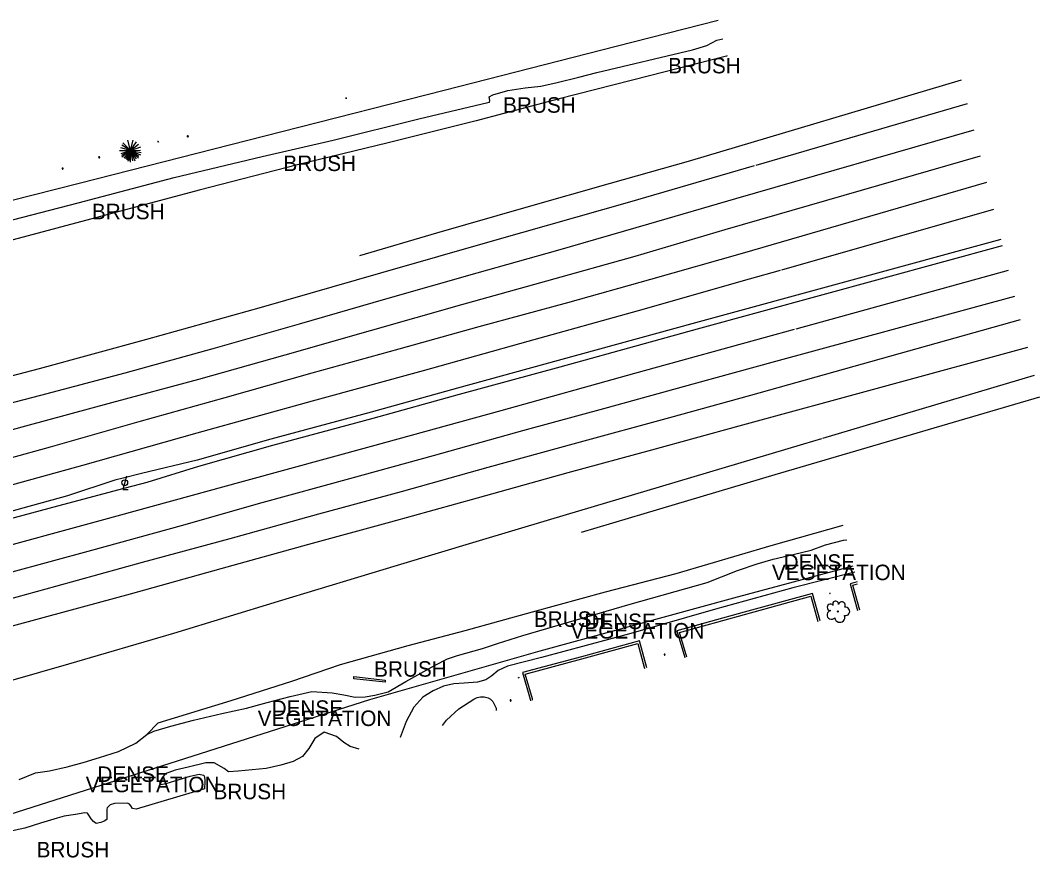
# Model space of a CAD drawing. Extents: x 2129547 to 2134906, y 657330 to 659734.
# Drawn here: x 2134392.5 to 2134852.3, y 658897.8 to 659275.8 of the extents above; entities that cross this region are included whole.
import ezdxf

# ---------------------------------------------------------------- set-up
doc = ezdxf.new("R2010")
doc.units = 0
for name, color, linetype in [('DR_X_Culvert', 7, 'Continuous'), ('LT_X_Poles', 7, 'Continuous'), ('PM_X_Edge_Line', 7, 'Continuous'), ('PM_X_Lane_Line', 7, 'Continuous'), ('PV_X_Curb', 7, 'Continuous'), ('PV_X_EOP', 7, 'Continuous'), ('PV_X_Parking_Lot', 7, 'Continuous'), ('PV_X_Shoulder', 7, 'Continuous'), ('RD_X_Concrete_Barrier', 7, 'Continuous'), ('RD_X_Fence', 7, 'Continuous'), ('VG_X_Cells', 7, 'Continuous'), ('VG_X_Flower_Bed', 7, 'Continuous'), ('VG_X_Shrub_Line_Lt', 7, 'Continuous'), ('VG_X_Text', 7, 'Continuous'), ('VG_X_Tree_Line_Lt', 7, 'Continuous')]:
    doc.layers.add(name, color=color, linetype=linetype)

msp = doc.modelspace()

# ---------------------------------------------------------------- linework, layer by layer
at = {"layer": 'DR_X_Culvert'}
msp.add_lwpolyline([(2134557, 658977), (2134542.86, 658978.58), (2134542.97, 658979.58), (2134557.11, 658977.99)], close=True, dxfattribs=at)
at = {"layer": 'LT_X_Poles'}
for points in [[(2134440.31, 659070.03), (2134438.74, 659064.05), (2134441.1, 659064.05)], [(2134757.71, 659017.31), (2134757.64, 659017.01), (2134757.75, 659017.01)], [(2134617.32, 658979.24), (2134617.24, 658978.94), (2134617.36, 658978.94)]]:
    msp.add_lwpolyline(points, dxfattribs=at)
for centre, radius in [((2134439.53, 659067.08), 1.3), ((2134757.68, 659017.16), 0.065), ((2134617.28, 658979.09), 0.065)]:
    msp.add_circle(centre, radius, dxfattribs=at)
at = {"layer": 'PM_X_Edge_Line'}
for points in [[(2134723.56, 659210.16), (2134667.28, 659193.75), (2134606.38, 659176.46), (2134554.94, 659161.67), (2134501.09, 659146.16), (2134449.29, 659131.67), (2134400.95, 659118.53), (2134356.58, 659106.88), (2134317.3, 659096.98), (2134285.7, 659088.97), (2134246.38, 659079.32), (2134241.17, 659078.04)], [(2134735.23, 659162.91), (2134721.25, 659158.93), (2134671.25, 659144.73), (2134621.41, 659130.82), (2134574.26, 659117.65), (2134524.14, 659103.87), (2134472.09, 659089.42), (2134420.46, 659074.83), (2134368.59, 659060.49), (2134308.4, 659043.65), (2134263.44, 659031.51), (2134253.36, 659028.71)], [(2134259.57, 659003.55), (2134296.43, 659013.77), (2134319.19, 659019.98), (2134374.37, 659035.23), (2134428.42, 659049.97), (2134493.16, 659067.81), (2134550.8, 659083.53), (2134609.4, 659099.69), (2134669.62, 659116.56), (2134732.99, 659133.95), (2134741.79, 659136.38)], [(2134274.16, 658944.52), (2134293.12, 658950.08), (2134329.98, 658961.06), (2134360.83, 658969.97), (2134414.34, 658985.33), (2134461.66, 658999.2), (2134508.88, 659013.57), (2134562.68, 659029.83), (2134598.06, 659040.48), (2134631.84, 659050.6), (2134687.93, 659067.36), (2134745.97, 659084.59), (2134753.99, 659086.98)]]:
    msp.add_lwpolyline(points, dxfattribs=at)
at = {"layer": 'PM_X_Lane_Line'}
for points in [[(2134822.61, 659226.18), (2134715.05, 659195.24), (2134675.81, 659183.86), (2134634.77, 659171.94), (2134598.34, 659161.72), (2134557.15, 659150), (2134518.25, 659138.64), (2134480.37, 659127.86), (2134439.61, 659116.6), (2134401.46, 659106.44), (2134359.78, 659095.67), (2134309.38, 659082.83), (2134275.7, 659074.42), (2134243.98, 659066.66)], [(2134825.5, 659214.49), (2134710.32, 659181.19), (2134669.66, 659169.26), (2134629.87, 659158.12), (2134591.41, 659147.43), (2134550.2, 659135.64), (2134511.72, 659124.67), (2134472.82, 659113.69), (2134433.56, 659103.17), (2134394.83, 659092.62), (2134356.4, 659082.11), (2134319.87, 659072.09), (2134283.72, 659062.12), (2134247.56, 659052.18)], [(2134828.43, 659202.6), (2134718.15, 659170.59), (2134676.73, 659158.78), (2134639.29, 659148.33), (2134599.33, 659137.45), (2134563.14, 659127.36), (2134524.01, 659116.49), (2134484.69, 659105.4), (2134445.95, 659094.5), (2134405.86, 659083.18), (2134368.79, 659072.88), (2134329.51, 659062.05), (2134290.35, 659051.26), (2134252.68, 659040.78), (2134250.52, 659040.2)], [(2134262.4, 658992.11), (2134275.67, 658995.74), (2134315.3, 659006.74), (2134348.87, 659015.75), (2134387.16, 659026.4), (2134424.62, 659036.65), (2134465.1, 659047.8), (2134501.55, 659058.17), (2134541.08, 659069), (2134578.8, 659079.33), (2134619.16, 659090.65), (2134657.36, 659101.1), (2134696.06, 659111.65), (2134733.24, 659121.93), (2134841.12, 659151.25)], [(2134265.12, 658981.08), (2134282.76, 658985.93), (2134321.9, 658996.69), (2134368.99, 659009.55), (2134408.45, 659020.37), (2134447.57, 659031.13), (2134487.07, 659041.95), (2134527.16, 659053), (2134564.44, 659063.14), (2134603.55, 659074.07), (2134643.47, 659085.14), (2134685.5, 659096.55), (2134722.02, 659106.56), (2134843.73, 659140.7)], [(2134846.83, 659128.14), (2134716.56, 659092.63), (2134677.17, 659081.8), (2134639.44, 659071.51), (2134598.52, 659060.07), (2134559.43, 659049.32), (2134522.49, 659039.2), (2134482.86, 659028.13), (2134442.03, 659016.71), (2134404.17, 659006.55), (2134363.13, 658995.42), (2134313.89, 658982.15), (2134271.17, 658970.33), (2134268, 658969.46)]]:
    msp.add_lwpolyline(points, dxfattribs=at)
at = {"layer": 'PV_X_Curb'}
for points in [[(2134769.96, 659022.37), (2134766.88, 659021.49), (2134770.22, 659009.31)], [(2134753.29, 659004.71), (2134749.79, 659017.01), (2134718.95, 659008.56), (2134688.65, 659000.16), (2134692.18, 658988.1)], [(2134675.06, 658983.45), (2134671.73, 658995.64), (2134645.59, 658988.52), (2134618.99, 658981.33), (2134622.51, 658969.34), (2134622.6, 658968.66)]]:
    msp.add_lwpolyline(points, dxfattribs=at)
at = {"layer": 'PV_X_EOP'}
for p, q in [((2134819.64, 659238.18), (2134724.23, 659210.35)), ((2134831.46, 659190.35), (2134735.86, 659163.09)), ((2134742.44, 659136.56), (2134838.21, 659163.02)), ((2134754.5, 659087.14), (2134849.94, 659115.57))]:
    msp.add_line(p, q, dxfattribs=at)
at = {"layer": 'PV_X_Parking_Lot'}
for points in [[(2134771.19, 659009.58), (2134768.11, 659020.8), (2134770.2, 659021.4)], [(2134693.14, 658988.37), (2134689.89, 658999.47), (2134719.22, 659007.59), (2134749.09, 659015.79), (2134752.33, 659004.45)], [(2134623.57, 658968.94), (2134623.49, 658969.55), (2134620.24, 658980.63), (2134645.85, 658987.55), (2134671.03, 658994.42), (2134674.1, 658983.19)]]:
    msp.add_lwpolyline(points, dxfattribs=at)
at = {"layer": 'PV_X_Shoulder'}
for points in [[(2134816.88, 659248.86), (2134693.73, 659212.03), (2134658.59, 659202.13), (2134620.53, 659191.28), (2134580.16, 659179.66), (2134545.46, 659169.48)], [(2134852.32, 659105.7), (2134732.93, 659070.57), (2134673.81, 659053.06), (2134645.44, 659044.63)]]:
    msp.add_lwpolyline(points, dxfattribs=at)
at = {"layer": 'RD_X_Concrete_Barrier'}
for points in [[(2134834.78, 659176.9), (2134697, 659139.23), (2134635.06, 659122.19), (2134589.66, 659109.73), (2134550.72, 659098.97), (2134505.43, 659086.73), (2134472.19, 659077.25), (2134447.11, 659071.29), (2134438.78, 659069.08), (2134435.09, 659068.21), (2134413.68, 659061.14), (2134357.43, 659045.64), (2134311.42, 659032.39), (2134266.53, 659020.26), (2134256.16, 659017.38)], [(2134835.5, 659173.98), (2134697.79, 659136.33), (2134635.86, 659119.29), (2134590.45, 659106.84), (2134551.51, 659096.07), (2134506.21, 659083.83), (2134472.85, 659074.37), (2134449.45, 659067.1), (2134436.3, 659063.72), (2134405.29, 659055.38), (2134358.24, 659042.75), (2134312.22, 659029.5), (2134267.32, 659017.37), (2134256.88, 659014.47)]]:
    msp.add_lwpolyline(points, dxfattribs=at)
at = {"layer": 'RD_X_Fence'}
for points in [[(2134707.34, 659275.8), (2134661.3, 659263.97), (2134583.68, 659244.07), (2134510.36, 659225.5), (2134418.95, 659202.15), (2134325.8, 659178.53), (2134239.8, 659158.08)], [(2134330.51, 658899.2), (2134411.41, 658924.97), (2134550.15, 658969.27), (2134626.91, 658991.22), (2134714.37, 659015.06), (2134768.19, 659029.53)]]:
    msp.add_lwpolyline(points, dxfattribs=at)
at = {"layer": 'VG_X_Cells'}
for p, q in [((2134539.22, 659240.71), (2134539.46, 659240.71)), ((2134539.46, 659240.71), (2134539.24, 659240.77)), ((2134539.46, 659240.71), (2134539.25, 659240.64)), ((2134539.46, 659240.71), (2134539.26, 659240.6)), ((2134539.46, 659240.71), (2134539.27, 659240.83)), ((2134539.46, 659240.71), (2134539.27, 659240.56)), ((2134539.46, 659240.71), (2134539.29, 659240.89)), ((2134539.46, 659240.71), (2134539.32, 659240.54)), ((2134539.46, 659240.71), (2134539.35, 659240.51)), ((2134539.46, 659240.71), (2134539.38, 659240.5)), ((2134539.46, 659240.71), (2134539.4, 659240.94)), ((2134539.46, 659240.71), (2134539.4, 659240.47)), ((2134539.46, 659240.71), (2134539.44, 659240.48)), ((2134539.46, 659240.71), (2134539.53, 659240.95)), ((2134539.46, 659240.71), (2134539.6, 659240.91)), ((2134539.46, 659240.71), (2134539.65, 659240.85)), ((2134539.46, 659240.71), (2134539.7, 659240.79)), ((2134539.46, 659240.71), (2134539.69, 659240.72)), ((2134539.46, 659240.45), (2134539.46, 659240.71)), ((2134539.46, 659240.71), (2134539.51, 659240.48)), ((2134539.46, 659240.71), (2134539.56, 659240.48)), ((2134539.46, 659240.71), (2134539.59, 659240.52)), ((2134539.46, 659240.71), (2134539.64, 659240.54)), ((2134539.46, 659240.71), (2134539.66, 659240.59)), ((2134539.46, 659240.71), (2134539.69, 659240.62)), ((2134539.46, 659240.71), (2134539.71, 659240.67)), ((2134442.13, 659217.09), (2134440.9, 659221.7)), ((2134442.13, 659217.09), (2134443.39, 659221.79)), ((2134442.13, 659217.09), (2134444.79, 659220.97)), ((2134454.35, 659221.1), (2134454.6, 659221.1)), ((2134454.6, 659221.1), (2134454.38, 659221.16)), ((2134454.6, 659221.1), (2134454.39, 659221.02)), ((2134454.6, 659221.1), (2134454.4, 659220.98)), ((2134454.6, 659221.1), (2134454.41, 659221.21)), ((2134454.6, 659221.1), (2134454.41, 659220.95)), ((2134454.6, 659221.1), (2134454.43, 659221.27)), ((2134454.6, 659221.1), (2134454.45, 659220.93)), ((2134454.6, 659221.1), (2134454.49, 659220.9)), ((2134454.6, 659221.1), (2134454.52, 659220.88)), ((2134454.6, 659221.1), (2134454.54, 659221.33)), ((2134454.6, 659221.1), (2134454.54, 659220.86)), ((2134454.6, 659221.1), (2134454.57, 659220.87)), ((2134454.6, 659221.1), (2134454.66, 659221.33)), ((2134454.6, 659221.1), (2134454.73, 659221.29)), ((2134454.6, 659221.1), (2134454.78, 659221.24)), ((2134454.6, 659221.1), (2134454.84, 659221.18)), ((2134454.6, 659220.84), (2134454.6, 659221.1)), ((2134454.6, 659221.1), (2134454.65, 659220.87)), ((2134454.6, 659221.1), (2134454.7, 659220.87)), ((2134454.6, 659221.1), (2134454.73, 659220.91)), ((2134454.6, 659221.1), (2134454.78, 659220.92)), ((2134454.6, 659221.1), (2134454.79, 659220.97)), ((2134454.6, 659221.1), (2134454.82, 659221)), ((2134454.6, 659221.1), (2134454.84, 659221.05)), ((2134454.6, 659221.1), (2134454.83, 659221.1)), ((2134437.2, 659217.09), (2134442.13, 659217.09)), ((2134442.13, 659217.09), (2134437.72, 659218.27)), ((2134442.13, 659217.09), (2134437.84, 659215.53)), ((2134442.13, 659217.09), (2134438.15, 659214.81)), ((2134442.13, 659217.09), (2134438.23, 659219.39)), ((2134442.13, 659217.09), (2134438.23, 659214.09)), ((2134442.13, 659217.09), (2134438.64, 659220.58)), ((2134442.13, 659217.09), (2134439.19, 659213.62)), ((2134442.13, 659217.09), (2134439.82, 659213.07)), ((2134442.13, 659217.09), (2134440.47, 659212.75)), ((2134442.13, 659217.09), (2134440.87, 659212.23)), ((2134442.13, 659217.09), (2134441.59, 659212.5)), ((2134442.13, 659217.09), (2134445.79, 659219.89)), ((2134442.13, 659217.09), (2134446.87, 659218.7)), ((2134442.13, 659217.09), (2134446.64, 659217.18)), ((2134442.13, 659211.85), (2134442.13, 659217.09)), ((2134442.13, 659217.09), (2134443.06, 659212.45)), ((2134442.13, 659217.09), (2134444.07, 659212.42)), ((2134442.13, 659217.09), (2134444.67, 659213.3)), ((2134442.13, 659217.09), (2134445.72, 659213.57)), ((2134442.13, 659217.09), (2134445.96, 659214.53)), ((2134442.13, 659217.09), (2134446.6, 659215.15)), ((2134442.13, 659217.09), (2134446.96, 659216.13))]:
    msp.add_line(p, q, dxfattribs=at)
for centre, radius in [((2134468, 659223.47), 0.012), ((2134428, 659213.99), 0.012), ((2134411.47, 659208.92), 0.012), ((2134761.26, 659008.92), 0.24), ((2134683.12, 658989.49), 0.012), ((2134613.62, 658968.74), 0.012), ((2134613.64, 658968.86), 0.012)]:
    msp.add_circle(centre, radius, dxfattribs=at)
for centre, radius, start, end in [((2134467.83, 659223.56), 0.0735, 39.0625, 279.5412), ((2134467.85, 659223.39), 0.0987, 96.1722, 320.5737), ((2134467.95, 659223.64), 0.0658, 354.0047, 205.9741), ((2134468.04, 659223.34), 0.114, 184.9476, 19.4572), ((2134468.09, 659223.61), 0.0776, 323.83, 165.0376), ((2134468.17, 659223.47), 0.0957, 259.1453, 101.4596), ((2134427.84, 659214.09), 0.0735, 39.0625, 279.5412), ((2134427.86, 659213.92), 0.0987, 96.1722, 320.5737), ((2134427.95, 659214.16), 0.0658, 354.0047, 205.9741), ((2134428.05, 659213.86), 0.114, 184.9476, 19.4572), ((2134428.09, 659214.14), 0.0776, 323.83, 165.0376), ((2134428.18, 659214), 0.0957, 259.1453, 101.4596), ((2134411.33, 659208.84), 0.0987, 96.1722, 320.5737), ((2134411.31, 659209.01), 0.0735, 39.0625, 279.5412), ((2134411.43, 659209.09), 0.0658, 354.0047, 205.9741), ((2134411.52, 659208.79), 0.114, 184.9476, 19.4572), ((2134411.57, 659209.06), 0.0776, 323.83, 165.0376), ((2134411.65, 659208.92), 0.0957, 259.1453, 101.4596), ((2134758.4, 659007.37), 1.97, 96.1722, 320.5737), ((2134757.95, 659010.79), 1.47, 39.0625, 279.5412), ((2134760.27, 659012.29), 1.32, 354.0047, 205.9741), ((2134763.08, 659011.75), 1.55, 323.83, 165.0376), ((2134764.72, 659008.96), 1.91, 259.1453, 101.4596), ((2134762.2, 659006.32), 2.28, 184.9476, 19.4572), ((2134682.96, 658989.58), 0.0735, 39.0625, 279.5412), ((2134682.98, 658989.41), 0.0987, 96.1722, 320.5737), ((2134683.07, 658989.65), 0.0658, 354.0047, 205.9741), ((2134683.17, 658989.36), 0.114, 184.9476, 19.4572), ((2134683.21, 658989.63), 0.0776, 323.83, 165.0376), ((2134683.3, 658989.49), 0.0957, 259.1453, 101.4596), ((2134613.46, 658968.83), 0.0735, 39.0625, 279.5412), ((2134613.48, 658968.66), 0.0987, 96.1722, 320.5737), ((2134613.47, 658968.95), 0.0735, 39.0625, 279.5412), ((2134613.5, 658968.78), 0.0987, 96.1722, 320.5737), ((2134613.57, 658968.91), 0.0658, 354.0047, 205.9741), ((2134613.59, 658969.03), 0.0658, 354.0047, 205.9741), ((2134613.67, 658968.61), 0.114, 184.9476, 19.4572), ((2134613.69, 658968.73), 0.114, 184.9476, 19.4572), ((2134613.71, 658968.88), 0.0776, 323.83, 165.0376), ((2134613.73, 658969), 0.0776, 323.83, 165.0376), ((2134613.8, 658968.74), 0.0957, 259.1453, 101.4596), ((2134613.81, 658968.86), 0.0957, 259.1453, 101.4596)]:
    msp.add_arc(centre, radius, start, end, dxfattribs=at)
at = {"layer": 'VG_X_Flower_Bed'}
msp.add_lwpolyline([(2134582.93, 658957.45), (2134584.72, 658959.91), (2134590.33, 658965.02), (2134597.01, 658969.32), (2134598.55, 658970.1), (2134600.01, 658970.33), (2134601.69, 658970.34), (2134603.58, 658969.98), (2134604.54, 658969.3), (2134605.55, 658968.32), (2134606.27, 658967.12), (2134607.05, 658965.3), (2134607.09, 658964.35), (2134607.08, 658964.28)], dxfattribs=at)
at = {"layer": 'VG_X_Shrub_Line_Lt'}
for points in [[(2134380.68, 659183.69), (2134418.55, 659193.46), (2134461.91, 659204.84), (2134501.5, 659214.36), (2134533.51, 659221.68), (2134572.17, 659231.34), (2134603.37, 659238.74), (2134604.04, 659238.89), (2134604.23, 659239.62), (2134604, 659241.34), (2134605.63, 659242.14), (2134612.37, 659244.07), (2134620.28, 659245.27), (2134627.29, 659246.07), (2134634.72, 659247.8), (2134644.48, 659250.13), (2134652.5, 659252.26), (2134695.74, 659262.44), (2134702.16, 659264.44), (2134706.7, 659266.82), (2134709.42, 659267.4)], [(2134711.3, 659259.78), (2134711.08, 659259.71), (2134676.33, 659250.7), (2134635.58, 659240.44), (2134598.06, 659230.48), (2134558.43, 659220.49), (2134517.52, 659210.54), (2134473.14, 659199.12), (2134428.66, 659187.23), (2134389.19, 659176.66), (2134342.91, 659164.6), (2134302.43, 659154.14), (2134260.35, 659143.37), (2134232.89, 659135.68)], [(2134449.5, 658953.41), (2134454.68, 658958.73), (2134487.62, 658968.73), (2134515, 658977.48), (2134536.93, 658985.07), (2134567.35, 658993.57), (2134593.13, 659000.32), (2134623.55, 659008.82), (2134656.38, 659017.75), (2134688.3, 659026.08), (2134731.19, 659038.79), (2134763.66, 659047.86)]]:
    msp.add_lwpolyline(points, dxfattribs=at)
at = {"layer": 'VG_X_Tree_Line_Lt'}
for points in [[(2134391.94, 658933.13), (2134399.24, 658936.15), (2134405.63, 658937.04), (2134413.56, 658938.73), (2134420.82, 658940.79), (2134428.21, 658943.09), (2134436.76, 658945.75), (2134444.5, 658949.45), (2134449.5, 658953.41), (2134452.62, 658954.88), (2134460.29, 658957.12), (2134470.59, 658959.81), (2134483.28, 658962.94), (2134494.52, 658965.32), (2134503.77, 658967.78), (2134514.23, 658970.61), (2134523.9, 658972.85), (2134533.08, 658972.17), (2134538.43, 658971.25), (2134543.51, 658970.25), (2134548.07, 658970.46), (2134552.35, 658971.15), (2134558.36, 658972.6), (2134566.36, 658977.38), (2134573.08, 658981.14), (2134579.58, 658984.71), (2134585.24, 658987.6), (2134589.66, 658989.08), (2134600.98, 658992.18), (2134607.7, 658994.53), (2134619.19, 658998.12), (2134667.59, 659012.2), (2134702.36, 659022.05), (2134715.98, 659027.49), (2134724.91, 659030.41), (2134732.04, 659032.57), (2134741.14, 659034.62), (2134749.19, 659036.66), (2134755.78, 659039.04), (2134763.91, 659041.14), (2134765.29, 659041.24)], [(2134768.89, 659026.67), (2134741.01, 659019.67), (2134706.1, 659009.94), (2134667.95, 658998.97), (2134627.62, 658988.22), (2134612.25, 658984.23), (2134607.96, 658982.32), (2134605.22, 658979.85), (2134602.44, 658978.12), (2134598.63, 658977.02), (2134592.73, 658976.53), (2134588.06, 658976.25), (2134583.37, 658975.26), (2134578.75, 658973.1), (2134573.98, 658970.28), (2134569.96, 658965.76), (2134566.59, 658959.23), (2134563.74, 658952.1), (2134563.75, 658952.02)], [(2134545.29, 658946.8), (2134541.2, 658947.94), (2134538.41, 658949.74), (2134535.07, 658952.57), (2134529.57, 658954.41), (2134525.38, 658951.66), (2134522.56, 658947.08), (2134519.73, 658943.47), (2134515.52, 658941.22), (2134510.03, 658939.52), (2134503.4, 658938.03), (2134490.74, 658936.83), (2134486.3, 658936.52), (2134484.39, 658938.06), (2134479.82, 658940.64), (2134476.08, 658940.59), (2134468.13, 658938.63), (2134462.3, 658937.34), (2134457.79, 658935.69), (2134455.99, 658933.18), (2134455.27, 658931.65), (2134455.6, 658930.88), (2134458.29, 658931.35), (2134464.09, 658933.11), (2134469.11, 658934.57), (2134473.07, 658935.51), (2134475.14, 658935.11), (2134475.44, 658934.7), (2134475.66, 658933.1), (2134475.67, 658932.25), (2134475.57, 658928.89), (2134444.66, 658919.7), (2134443.03, 658919.98), (2134442.22, 658921.23), (2134441.72, 658921.92), (2134440.72, 658922.39), (2134434.96, 658922.2), (2134433.03, 658921.65), (2134431.56, 658920.31), (2134431.4, 658919.69), (2134431.5, 658917.93), (2134431.48, 658916.71), (2134431.51, 658915.02), (2134430.25, 658914.21), (2134428.73, 658913.6), (2134426.65, 658913.15), (2134425.42, 658914.08), (2134424.43, 658915.38), (2134423.62, 658916.58), (2134422.7, 658917.89), (2134421.48, 658917.96), (2134417.39, 658917.33), (2134412.23, 658916.47), (2134408.99, 658915.59), (2134406.06, 658914.68), (2134401.59, 658913.34), (2134394.48, 658911.11), (2134386.77, 658909.44)]]:
    msp.add_lwpolyline(points, dxfattribs=at)

# ---------------------------------------------------------------- texts
at = {"layer": 'VG_X_Text'}
for s, p in [('BRUSH', (2134684.72, 659251.88)), ('BRUSH', (2134610.26, 659234.1)), ('BRUSH', (2134511.15, 659207.77)), ('BRUSH', (2134424.73, 659186)), ('DENSE', (2134736.8, 659027.74)), ('VEGETATION', (2134731.54, 659023.08)), ('BRUSH', (2134624.14, 659001.99)), ('DENSE', (2134646.91, 659001)), ('VEGETATION', (2134640.72, 658996.73)), ('BRUSH', (2134552.06, 658979.5)), ('DENSE', (2134505.81, 658961.81)), ('VEGETATION', (2134499.53, 658957.23)), ('DENSE', (2134427.21, 658931.98)), ('VEGETATION', (2134421.96, 658927.32)), ('BRUSH', (2134479.59, 658924.15)), ('BRUSH', (2134399.78, 658897.91))]:
    msp.add_text(s, height=7, dxfattribs=at).set_placement(p)

doc.saveas('drawing.dxf')
